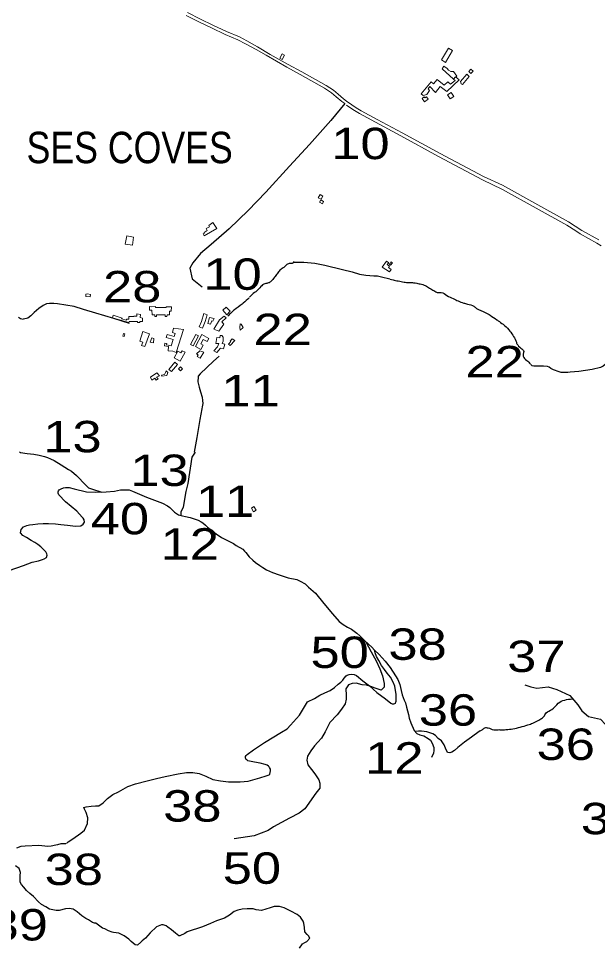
# Model space of a CAD drawing. Extents: x 476989 to 498418, y 4381813 to 4416555.
# Drawn here: x 484677 to 485599, y 4385658 to 4387137 of the extents above; entities that cross this region are included whole.
import ezdxf
from ezdxf.enums import TextEntityAlignment as Align

# ---------------------------------------------------------------- set-up
doc = ezdxf.new("R2010")
doc.units = 0
doc.header["$LTSCALE"] = 20
doc.linetypes.add('MEDIUM_DASHED', pattern=[4.5, 3, -1.5])
for name, color, linetype, lineweight in [('13', 7, 'Continuous', 13), ('36', 7, 'Continuous', 13), ('47', 7, 'Continuous', 13), ('48', 7, 'MEDIUM_DASHED', 13), ('6', 7, 'Continuous', 25)]:
    doc.layers.add(name, color=color, linetype=linetype, lineweight=lineweight)
doc.layers.add('7', color=7, linetype='Continuous')

msp = doc.modelspace()

# ---------------------------------------------------------------- linework, layer by layer
at = {"layer": '36'}
for points in [[(484944.1, 4387141.99), (484964.47, 4387131.61), (484984.32, 4387121.95), (485006.12, 4387111.66), (485026.67, 4387103.08), (485038.55, 4387096.84), (485055.45, 4387087.66), (485071.49, 4387078.37), (485104.22, 4387059.29), (485125.9, 4387047.57), (485164.72, 4387025.8), (485175.49, 4387018.62), (485182.86, 4387012.44), (485191.84, 4387004.83), (485196.68, 4387001.41)], [(484946.46, 4387146.48), (484966.73, 4387136.15), (484986.51, 4387126.53), (485008.19, 4387116.3), (485028.83, 4387107.68), (485040.94, 4387101.32), (485057.93, 4387092.09), (485077.85, 4387079.8), (485106.7, 4387063.72), (485128.35, 4387052.02), (485167.37, 4387030.13), (485178.54, 4387022.69), (485186.13, 4387016.32), (485194.95, 4387008.84), (485199.56, 4387005.59), (485207.95, 4386999.32), (485214.97, 4386994.81), (485222.72, 4386990.21), (485248.09, 4386976.31), (485288.29, 4386954.73), (485348.62, 4386921.76), (485417.64, 4386885.14), (485448.2, 4386871.57)], [(485199.66, 4386999.18), (485205.06, 4386995.15), (485212.3, 4386990.49), (485220.21, 4386985.8), (485245.67, 4386971.85), (485285.88, 4386950.27), (485346.2, 4386917.3), (485416.17, 4386880.07), (485448.2, 4386864.89)], [(485448.2, 4386871.57), (485504.34, 4386840.28), (485553.22, 4386813.06), (485574.47, 4386799.34), (485601.49, 4386784.39)], [(485448.2, 4386864.89), (485501.51, 4386835.18), (485550.21, 4386808.06), (485564.49, 4386798.84)], [(485564.49, 4386798.84), (485571.47, 4386794.33), (485598.37, 4386779.45), (485604.95, 4386774.75)]]:
    msp.add_lwpolyline(points, dxfattribs=at)
at = {"layer": '47'}
for points in [[(485097.24, 4387080.64), (485100.57, 4387078.42), (485096.97, 4387071.84), (485093.08, 4387073.8)], [(485368.22, 4387086.2), (485357.27, 4387067.19), (485350.67, 4387071.13), (485362.11, 4387089.78)], [(485391.11, 4387048.23), (485395.02, 4387044.71), (485384.02, 4387031.63), (485382.12, 4387032.82), (485380.94, 4387036.71)], [(485394.39, 4387052.63), (485397.68, 4387049.39), (485401.01, 4387052.87), (485397.7, 4387056.05)], [(485372.99, 4387044.3), (485379, 4387039.44), (485359.12, 4387020.48), (485348.48, 4387028.62), (485341.4, 4387019.09), (485332.09, 4387028.81), (485329.57, 4387025.05), (485331.9, 4387022.2), (485327.68, 4387016.19), (485321.58, 4387014.58), (485318.65, 4387016.84), (485334.49, 4387035.93), (485338.08, 4387032.94), (485343.81, 4387040.06), (485355.18, 4387030.96), (485360.7, 4387036.3), (485365.34, 4387032.5), (485372.61, 4387038.49), (485370.16, 4387040.56)], [(485366.04, 4387018.89), (485370.57, 4387012.53), (485364.64, 4387009.06), (485360.3, 4387015.36)], [(485327, 4387012.45), (485329.8, 4387008.42), (485323.53, 4387004.21), (485319.77, 4387009.59), (485323.16, 4387012.07), (485324.25, 4387010.89)], [(485159.11, 4386849.19), (485161.77, 4386854.02), (485157.33, 4386856.45), (485154.56, 4386851.45)], [(485158.77, 4386848.3), (485163.02, 4386845.74), (485161.19, 4386841.81), (485156.57, 4386844.26)], [(484986.77, 4386812.07), (484993.03, 4386802.65), (484972.62, 4386790.82), (484971.23, 4386794), (484973.4, 4386795.11), (484972.72, 4386796.45), (484977.43, 4386799.32), (484975.89, 4386802.33), (484981.16, 4386805.24), (484980.03, 4386807.2)], [(484849.44, 4386790.77), (484846.94, 4386777.85), (484858.51, 4386775.82), (484860.5, 4386788.91)], [(485267.8, 4386733.43), (485256.48, 4386741.12), (485263.36, 4386750.59), (485266.67, 4386747.96), (485264.52, 4386745.08), (485268.18, 4386742.35), (485266.49, 4386740.36), (485270.62, 4386737.25)], [(485272.72, 4386747.91), (485269.84, 4386744.21), (485268.02, 4386745.4), (485269.25, 4386747.04), (485268.91, 4386747.33), (485270.37, 4386749.54)], [(484791.59, 4386697.69), (484791.41, 4386693.78), (484784.36, 4386694.03), (484784.57, 4386697.72), (484787.22, 4386698.3)], [(484874.65, 4386654.69), (484870.48, 4386654.58), (484870.46, 4386653.02), (484866.58, 4386653.01), (484866.49, 4386654.59), (484853.21, 4386654.39), (484852.68, 4386652.83), (484826.61, 4386660.29), (484827.71, 4386664.28), (484842.06, 4386659.71), (484841.42, 4386658.6), (484849.07, 4386656.47), (484849.11, 4386658.07), (484852.95, 4386658.16), (484852.97, 4386662.54), (484860.65, 4386662.23), (484860.59, 4386662.87), (484865.39, 4386662.92), (484865.39, 4386666.55), (484871.56, 4386665.85), (484871.09, 4386660.58), (484874.62, 4386659.92)], [(484912.38, 4386677.94), (484920.75, 4386677.78), (484920.46, 4386671.05), (484917.81, 4386671.05), (484917.39, 4386664.88), (484913.7, 4386664.88), (484913.51, 4386662.27), (484910.67, 4386662.23), (484910.82, 4386664.83), (484896.88, 4386664.88), (484896.69, 4386662.27), (484894.26, 4386662.29), (484894.38, 4386664.94), (484889.81, 4386664.95), (484889.46, 4386672.4), (484885.79, 4386672.68), (484885.72, 4386678.1), (484888.41, 4386678.06), (484895.26, 4386678.11), (484895.2, 4386676.96), (484912.45, 4386676.68)], [(484965.07, 4386645.88), (484968.64, 4386654.55), (484972.34, 4386666.93), (484977.49, 4386665.02), (484974.53, 4386654.43), (484969.91, 4386643.72)], [(485009.06, 4386664.93), (485002.56, 4386672.56), (485007.64, 4386677.52), (485014.09, 4386671.17)], [(484982.82, 4386649.95), (484978.55, 4386651.27), (484981.38, 4386660.9), (484988.94, 4386659.2), (484986.79, 4386654.97), (484985.12, 4386655.57)], [(484996.43, 4386639.1), (484988.3, 4386642.47), (484997.48, 4386657.34), (485004.88, 4386662.98), (485007.91, 4386660.32), (485001.03, 4386653.8), (485004.26, 4386650.11)], [(485030.11, 4386650.61), (485029.58, 4386644.86), (485029.99, 4386640.89), (485034.75, 4386645), (485031.79, 4386649.97)], [(484844.5, 4386635.18), (484846.55, 4386634.63), (484845.65, 4386630.54), (484843.47, 4386631)], [(484878.58, 4386614.5), (484885.94, 4386635.06), (484875.22, 4386638.61), (484870.18, 4386623.37), (484875.16, 4386621.77), (484873.26, 4386616.47)], [(484928.18, 4386605.08), (484939.97, 4386641.51), (484923.72, 4386643.6), (484923.72, 4386643.6), (484922.15, 4386636.75), (484926.42, 4386635.39), (484924.89, 4386630.56), (484914.1, 4386633.92), (484912.38, 4386628.99), (484923.2, 4386626.01), (484920.36, 4386615.87), (484913.03, 4386617.33), (484913.16, 4386619.43), (484910.06, 4386619.81), (484909.64, 4386615.9), (484916.17, 4386614.67), (484915.69, 4386607.82), (484923.12, 4386607.18)], [(484963.89, 4386631.61), (484955.07, 4386615.72), (484950.82, 4386617.68), (484959.38, 4386633.93)], [(484886.83, 4386621.49), (484889.37, 4386628.45), (484892.44, 4386627.58), (484892, 4386620.32)], [(484967.69, 4386609.95), (484958.91, 4386614.38), (484968.97, 4386633.65), (484980.35, 4386627.47), (484977.58, 4386622.58), (484971.41, 4386625.97), (484967.47, 4386618.74), (484971.14, 4386616.66)], [(484988.42, 4386607.8), (484994.31, 4386613.95), (484996.03, 4386619.44), (484991.42, 4386619.37), (484993.16, 4386629.13), (484997.81, 4386628.54), (484998.06, 4386632.15), (485000.73, 4386632.13), (485003.26, 4386629.33), (485003.18, 4386623.16), (485001.26, 4386619.51), (485005.92, 4386618.3), (485003.83, 4386610.74), (484998.71, 4386611.89), (484992.95, 4386605.26)], [(485011.45, 4386618.18), (485014.46, 4386616.41), (485021.54, 4386624.32), (485017.31, 4386627), (485014.34, 4386623.18), (485015.15, 4386622.6)], [(484930.93, 4386607.22), (484924.86, 4386596.58), (484934.84, 4386591.38), (484942.38, 4386605.69), (484937.68, 4386607.95), (484935.78, 4386604.53)], [(484966.64, 4386595.92), (484972.22, 4386605.45), (484965.86, 4386607.86), (484960.42, 4386603.19), (484963.09, 4386601.11), (484961.54, 4386598.91)], [(484930.53, 4386586.08), (484920.88, 4386574.84), (484916.58, 4386578.14), (484926.15, 4386589.6)], [(484911.46, 4386573.35), (484909.91, 4386569.85), (484905.06, 4386569.06), (484905.54, 4386567.13), (484913.36, 4386568.57), (484915.04, 4386573.28), (484912.15, 4386575.78)], [(484931.93, 4386579.1), (484935.2, 4386575.97), (484938.33, 4386579.24), (484934.89, 4386582.26)], [(484897.59, 4386572.87), (484901.46, 4386567.77), (484897.1, 4386566.06), (484899.31, 4386562.89), (484896.16, 4386560.94), (484894.13, 4386564.12), (484889.43, 4386560.81), (484887.27, 4386565.75)]]:
    msp.add_lwpolyline(points, close=True, dxfattribs=at)
msp.add_lwpolyline([(485370.16, 4387040.56), (485352.1, 4387056.87), (485354.61, 4387061.18), (485359.78, 4387057.35), (485362.15, 4387054.85), (485365.59, 4387052.79), (485369.74, 4387052.73), (485375.25, 4387045.3), (485374.01, 4387043.48)], dxfattribs=at)
at = {"layer": '48'}
msp.add_lwpolyline([(485047.97, 4386357.07), (485051.39, 4386351.42), (485055.76, 4386354.03), (485052.03, 4386360.03)], close=True, dxfattribs=at)
at = {"layer": '6'}
for points in [[(485196.68, 4387001.41), (485174.53, 4386974.43), (485140.42, 4386936.16), (485108.67, 4386902.09), (485070.95, 4386860.47), (485042.96, 4386831.45), (485012.41, 4386802.17), (484984.19, 4386777.31), (484966.85, 4386762.96), (484954.68, 4386748.08), (484950.17, 4386739.57), (484953.68, 4386722.28), (484969.49, 4386709.51)], [(485115.8, 4386749.57), (485116.23, 4386749.1), (485119.88, 4386748.84), (485125.2, 4386748.79), (485131.48, 4386748.94), (485148.96, 4386747.36), (485165.08, 4386743.99), (485193.34, 4386737.28), (485208.6, 4386733.52), (485219.97, 4386729.79), (485230.45, 4386728.1), (485243, 4386727.43), (485248.7, 4386726.99), (485255.02, 4386725.5), (485268.69, 4386722.23)], [(484853.83, 4386651.43), (484829.07, 4386659.2), (484800.41, 4386667.98), (484780.66, 4386673.63), (484765.62, 4386678.12), (484752.26, 4386680.6), (484739.16, 4386682.53), (484733.6, 4386683.05), (484726.44, 4386683.19), (484721.56, 4386682.61), (484716.47, 4386680.06), (484709.49, 4386675.03), (484701.94, 4386668.98), (484696.71, 4386663.28), (484692.09, 4386660), (484689.62, 4386659.03), (484684.79, 4386658.31)], [(484677.03, 4386661.52), (484680.13, 4386659.31), (484684.79, 4386658.31)], [(484996.82, 4386599.17), (484987.66, 4386591.04), (484966.55, 4386571), (484963.37, 4386567.3), (484963.02, 4386566.37), (484962.82, 4386558.23), (484964.9, 4386549.85), (484966.92, 4386542.55), (484969.46, 4386533.86), (484970.42, 4386528.49), (484970.53, 4386524.01), (484969.46, 4386518.29), (484968.88, 4386515.18), (484965.99, 4386498.52), (484961.18, 4386469.77), (484956.92, 4386446.46)], [(485614.42, 4386588.88), (485608.24, 4386583.25), (485603.79, 4386581.02), (485590.67, 4386577.99), (485569.57, 4386574.82), (485555.53, 4386573.67), (485552.14, 4386573.42), (485549.36, 4386573.22), (485546.88, 4386573.26), (485541.5, 4386573.42), (485538.28, 4386574.27), (485529.3, 4386577.31), (485524.93, 4386579.57), (485522.13, 4386581.47), (485519.82, 4386582.6), (485513.12, 4386583.13), (485507.1, 4386583.36), (485502.68, 4386583.42), (485498.06, 4386583.56), (485495.44, 4386583.92), (485492.88, 4386586.05)], [(484678.9, 4386446.99), (484680.33, 4386445.85), (484691.09, 4386444.37), (484701.51, 4386443.23), (484710.08, 4386441.49), (484718.53, 4386439.37), (484723.57, 4386437.83), (484728.11, 4386435.66), (484734.03, 4386433), (484745.31, 4386426.03), (484756.55, 4386418.6), (484761.33, 4386415.93), (484769.5, 4386409.28), (484784.5, 4386393.85), (484788.56, 4386389.73), (484793.23, 4386388.09), (484809.87, 4386382.9)], [(484958.3, 4386446.26), (484953.04, 4386438.59), (484946.62, 4386396.38), (484943.54, 4386383.67), (484939.22, 4386358.89), (484937.9, 4386355.26), (484935.85, 4386351.35), (484935.78, 4386345.49)], [(484685.19, 4386265.93), (484699.05, 4386271.21), (484709.17, 4386273.3), (484715.34, 4386275.16), (484718.26, 4386276.38), (484721.48, 4386278.67), (484722.61, 4386282.28), (484722.26, 4386284.54), (484720.47, 4386287.55), (484712.75, 4386295.74), (484708.14, 4386299.06), (484702.94, 4386302.54), (484697.3, 4386305.69), (484689.87, 4386310.65), (484683.82, 4386313.61), (484680.3, 4386317.64), (484681.25, 4386322.94), (484685, 4386327.62), (484690.15, 4386329.65), (484694.88, 4386330.51), (484699.71, 4386331.42), (484707.82, 4386332.39), (484716.34, 4386332.7), (484724.64, 4386332.71), (484735.89, 4386332.21), (484744.5, 4386331.21), (484755.17, 4386329.99), (484767.77, 4386328.32), (484776.22, 4386328.88), (484780.04, 4386331.64), (484782.17, 4386335), (484781.89, 4386338.8), (484780.11, 4386341.21), (484778.3, 4386343.08), (484770.28, 4386352.19), (484752.12, 4386367.49), (484741.53, 4386378.26), (484740.11, 4386380.91), (484740.18, 4386383.41), (484740.83, 4386384.77), (484742.14, 4386386.31), (484744.9, 4386388.13), (484748.72, 4386389.71), (484752.02, 4386390.1), (484757.64, 4386389.92), (484765.75, 4386388.13), (484785.25, 4386383.31), (484799.6, 4386382.75), (484816.87, 4386383.07), (484829.76, 4386384.43), (484839.45, 4386386.17), (484849.35, 4386386.59), (484853.26, 4386386.23), (484858.54, 4386384.32), (484881.13, 4386374.95), (484906.55, 4386365.25), (484914.67, 4386360.86), (484918.39, 4386358.2), (484925.44, 4386350.65), (484931.98, 4386346.41), (484938.51, 4386345.07), (484942.87, 4386343.84)], [(484942.87, 4386343.84), (484950.32, 4386342.24), (484955.52, 4386340.89), (484963.01, 4386337.82), (484967.78, 4386335.39), (484970.48, 4386333.62), (484974.91, 4386330.09), (484978.3, 4386327.13), (484983.78, 4386322.85), (484991.83, 4386316.23), (485000.22, 4386310.65), (485010.22, 4386305.49), (485019.61, 4386300.9), (485023.89, 4386297.97), (485034.3, 4386291.84), (485037.17, 4386288.93), (485039.13, 4386286.4), (485044.46, 4386279.63), (485050.26, 4386274.45), (485054.6, 4386270.52), (485061.48, 4386265.69), (485066.31, 4386262.9), (485072.11, 4386258.98), (485081.56, 4386254.75), (485092.29, 4386251), (485106.38, 4386246.15), (485120.38, 4386243.3), (485125.75, 4386241.04), (485133.62, 4386236.48), (485138.8, 4386231.28), (485150.15, 4386221.79), (485163.42, 4386205.22), (485177.27, 4386188.83), (485187.8, 4386176.49), (485194.39, 4386172.03), (485200.95, 4386167.78), (485207.56, 4386164.49), (485215.71, 4386158.18), (485220.87, 4386153.67), (485228.5, 4386145.73), (485239.66, 4386135.6), (485243.92, 4386131.21)], [(484662.04, 4386258.08), (484685.19, 4386265.93)], [(485230.17, 4386144.48), (485238.93, 4386128.18), (485246.9, 4386114.26), (485252.47, 4386101.54), (485256.85, 4386090.01), (485259.24, 4386078.08), (485259.64, 4386072.11), (485254.86, 4386067.34), (485244.91, 4386070.52), (485238.14, 4386073.31), (485231.37, 4386075.3), (485224.2, 4386075.69), (485214.64, 4386078.48), (485208.67, 4386078.08), (485202.69, 4386075.69), (485198.31, 4386069.33), (485199.11, 4386059.57), (485198.71, 4386052.8), (485197.12, 4386045.64), (485191.54, 4386036.89), (485184.77, 4386028.13), (485173.22, 4386015.8), (485165.66, 4386001.18), (485159.68, 4385990.84), (485153.71, 4385984.47), (485148.53, 4385978.9), (485142.56, 4385970.54), (485137.38, 4385962.19), (485136.19, 4385955.82), (485138.18, 4385948.66), (485143.75, 4385941.1), (485149.33, 4385933.93), (485155.7, 4385924.38), (485156.89, 4385919), (485156.89, 4385911.43), (485150.92, 4385903.48), (485133, 4385878.41), (485124.24, 4385871.64), (485108.82, 4385863.4), (485083.33, 4385849.87), (485074.57, 4385843.9), (485052.27, 4385835.14), (485020.41, 4385830.77)], [(485137.42, 4386048.97), (485148.63, 4386053.82), (485157.15, 4386059.18), (485164.93, 4386062.86), (485173.69, 4386066.86), (485180.28, 4386071.55), (485186.41, 4386076.63), (485190.45, 4386080.03), (485193.63, 4386083.43), (485195.76, 4386086.35), (485199.08, 4386090.25), (485200.34, 4386091.24), (485203.86, 4386092.43), (485208.21, 4386092.7), (485211.9, 4386092.03), (485215.19, 4386090.42), (485225.5, 4386082.35), (485236.31, 4386074.25), (485247.96, 4386063.67), (485261.46, 4386053.34), (485269.97, 4386046.64), (485272.18, 4386045.77), (485274.75, 4386045.53), (485276.27, 4386045.91), (485277.39, 4386046.58), (485277.29, 4386046.46), (485277.27, 4386046.28), (485277.91, 4386048.23), (485278.42, 4386049.78), (485278.61, 4386055.69), (485278.62, 4386060.86), (485277.55, 4386067.01), (485276.23, 4386073.52), (485274, 4386079.95), (485269.68, 4386088.07), (485264.45, 4386094.26), (485259.77, 4386100.29), (485255.39, 4386106.74), (485251.08, 4386114.81), (485247.23, 4386121.17), (485244.96, 4386126.54), (485243.92, 4386131.21)], [(485244.01, 4386130.88), (485251.73, 4386124.05), (485261.17, 4386113.52), (485269.16, 4386103.38), (485277.47, 4386090.36), (485281.02, 4386084.45), (485284.58, 4386076.08), (485286.34, 4386066.85), (485288.02, 4386059.68), (485291.51, 4386051.58), (485293.26, 4386046.93), (485295.26, 4386040.29), (485298.32, 4386028.5), (485299.16, 4386022.88), (485301.83, 4386015.45), (485307.25, 4386003.05), (485311.27, 4385998.43), (485316.17, 4385996.13), (485322.45, 4385994.43), (485329.69, 4385990.5), (485333.27, 4385987.49), (485336.16, 4385982.91), (485338.39, 4385976.12), (485338.64, 4385971.4), (485337.85, 4385966.8), (485334.87, 4385960.03)], [(485483.32, 4386075.85), (485492.95, 4386072.64), (485502.59, 4386070.51), (485520.79, 4386072.64), (485534.7, 4386068.37), (485555.04, 4386058.75), (485567.89, 4386043.78), (485574.31, 4386034.16), (485585.02, 4386025.61), (485604.29, 4386021.34), (485611.78, 4386012.79), (485612.86, 4385999.96), (485619.28, 4385980.72)], [(484753.57, 4385823.35), (484756.07, 4385825.8), (484763.83, 4385830.53), (484776.58, 4385839.37), (484782.34, 4385844.43), (484787.2, 4385854.84), (484787.51, 4385863.86), (484784.87, 4385872.53), (484782.19, 4385877.63), (484780.99, 4385880.64), (484784.76, 4385881.31), (484793.02, 4385882.42), (484799.69, 4385882.89), (484804.87, 4385883.25), (484812.21, 4385887.91), (484818.61, 4385894.93), (484827.29, 4385900.91), (484836.49, 4385905.57), (484851.49, 4385914.04), (484863.4, 4385918.36), (484882.15, 4385922.96), (484896.7, 4385926.47), (484910.78, 4385929.65), (484931.26, 4385933.88), (484944.85, 4385936.14), (484954.98, 4385936.35), (484964.69, 4385934.66), (484975.5, 4385930.27), (484986.54, 4385925.21), (484998.58, 4385922.91), (485011.63, 4385921.23), (485030.11, 4385921.12), (485042.66, 4385922.44), (485061.41, 4385927.72), (485071.46, 4385930.94), (485074.81, 4385932.11), (485076.32, 4385932.73), (485076.79, 4385932.96), (485077.28, 4385933.45), (485078.11, 4385936.24), (485078.35, 4385938.73), (485078.24, 4385941.42), (485077.1, 4385943.96), (485076.09, 4385945.28), (485075.2, 4385946.11), (485073.05, 4385947.62), (485070.18, 4385948.95), (485061.85, 4385950.92), (485052.97, 4385952.73), (485042.57, 4385954.94), (485040.72, 4385956.12), (485039.31, 4385957.48), (485038.69, 4385959.31), (485038.59, 4385960.67), (485038.85, 4385961.89), (485039.56, 4385963.1), (485041.35, 4385965.05), (485051.42, 4385972.39), (485069, 4385983.72), (485096.24, 4386000.56), (485104.76, 4386005.49), (485110.15, 4386011.63), (485124.59, 4386027.56), (485137.59, 4386048.93)], [(485360.44, 4385967.89), (485357.02, 4385975.21), (485355.18, 4385980.08), (485350.75, 4385986.5), (485345.66, 4385990.53), (485341.11, 4385995.13), (485337.24, 4385997.82), (485332.38, 4385999.2), (485327.57, 4386000.86), (485318.71, 4386002.15), (485313.97, 4386002.06), (485308.63, 4386001.53)], [(485410.77, 4386001.69), (485398.53, 4385992.68), (485387.19, 4385984.33), (485376.75, 4385975.81), (485371.33, 4385971.08), (485367.37, 4385968.65), (485364.11, 4385967.7), (485360.44, 4385967.89)], [(484674.66, 4385816.15), (484681.59, 4385818.87), (484687.68, 4385819.41), (484687.98, 4385819.58), (484709.29, 4385820.21), (484723.73, 4385818.84), (484729.17, 4385819.65), (484736.43, 4385820.77), (484740.02, 4385821.59), (484744.86, 4385823.22), (484752.62, 4385823.08)], [(484800.3, 4385696.28), (484798.02, 4385696.13), (484794.95, 4385697.11), (484788.65, 4385701.33), (484784.14, 4385703.65), (484778.1, 4385707.87), (484770.66, 4385714.12), (484763.99, 4385718.53), (484757.75, 4385719.78), (484751.75, 4385719.07), (484741.98, 4385716.54), (484737.22, 4385716.32), (484726.74, 4385718.66), (484720.63, 4385722.11), (484713.97, 4385725.94), (484709.05, 4385730.17), (484700.76, 4385738.7), (484695.42, 4385743.75), (484690.09, 4385748.53), (484685.65, 4385753.67), (484681.68, 4385758.04), (484679.8, 4385761.6), (484679.52, 4385766.78), (484679.87, 4385772.29), (484680.17, 4385776.84), (484679.5, 4385780.26), (484677.94, 4385783.18), (484672.46, 4385787.45)], [(485124.79, 4385656.54), (485129.25, 4385663.08), (485133.36, 4385665.71), (485136.36, 4385667.21), (485141.15, 4385672.45), (485138.98, 4385676.34), (485136.6, 4385678.19), (485132.96, 4385682.34), (485132.73, 4385689.27), (485131.61, 4385696.11), (485130.61, 4385699.3), (485126.06, 4385705.79), (485120.96, 4385709.83), (485110.68, 4385715.36), (485102.13, 4385719.83), (485100.43, 4385720.52), (485092.99, 4385723.04), (485084.43, 4385722.63), (485077.87, 4385720.89), (485071.23, 4385718.34), (485064, 4385716.41), (485055.4, 4385717.72), (485051.11, 4385718.81), (485041.54, 4385719.28), (485033.36, 4385718.73), (485026.4, 4385717.08), (485020.65, 4385715.06), (485013.23, 4385708.97), (485004.94, 4385704.27), (484992.48, 4385699.86), (484982.68, 4385695.78), (484970.33, 4385690.54), (484945.93, 4385682.49), (484941.89, 4385679.67), (484934.03, 4385676.17), (484932.74, 4385676.12), (484927.13, 4385680.21), (484921, 4385685.64), (484914.97, 4385689.73), (484912.08, 4385691.8), (484907.48, 4385693.68), (484904.82, 4385693.81), (484897.05, 4385690.33), (484887.01, 4385681), (484879.15, 4385672.55), (484873.88, 4385668.07), (484872, 4385666.15), (484866.47, 4385661.44), (484862.95, 4385661.58), (484856.78, 4385667.28), (484853.08, 4385670.62), (484845.41, 4385676.06), (484837.17, 4385680.06), (484828.17, 4385681.33), (484826.1, 4385681.74), (484820.37, 4385683.92), (484814.41, 4385687.36), (484810.87, 4385688.46), (484804.79, 4385692.89), (484800.15, 4385696.36)]]:
    msp.add_lwpolyline(points, dxfattribs=at)
for points in [[(485115.36, 4386750.06), (485114.19, 4386747.52), (485113.18, 4386746.88), (485109.53, 4386746.71), (485104.69, 4386745.06), (485100.59, 4386741.44), (485096.18, 4386738.34), (485093.43, 4386736.08), (485088.97, 4386730.52), (485084.71, 4386724.86), (485079.08, 4386718.3), (485075.29, 4386715.77), (485069.5, 4386714.61), (485062.95, 4386709.95), (485056.92, 4386703.52), (485049.07, 4386697.32), (485044.98, 4386693.19)], [(485269.25, 4386721.86), (485273.58, 4386720.69), (485281.99, 4386718.99), (485291.13, 4386717.08), (485298.97, 4386716.54), (485306.16, 4386716.18), (485311.27, 4386715.46), (485318.78, 4386713.76), (485326.94, 4386710.61), (485333.63, 4386706.4), (485340.32, 4386702.69), (485343.71, 4386700.79), (485350.33, 4386700.57), (485359.32, 4386695.9), (485369.58, 4386690.94), (485377.37, 4386687.13), (485386.17, 4386683.79), (485392.17, 4386682.32), (485402.4, 4386678.62), (485406.74, 4386675.4), (485420.48, 4386668.69), (485428.53, 4386664.29), (485438.68, 4386657.3), (485441.05, 4386655.72), (485448.83, 4386650.03), (485458.08, 4386641.35), (485464.26, 4386632.88), (485469.2, 4386623.92), (485470.98, 4386618.97), (485477.37, 4386612.21), (485481.67, 4386606.48), (485480.65, 4386601.56), (485480.95, 4386599.19), (485486.47, 4386592.56), (485492.66, 4386586.48)], [(485044.48, 4386692.16), (485035.19, 4386683.87), (485033.34, 4386682.1), (485020.94, 4386672.97), (485016.38, 4386668.89), (485010.36, 4386663.05)], [(485443.74, 4386004.16), (485443.83, 4386004.15), (485453.51, 4386004.46), (485464.41, 4386005.81), (485476.23, 4386008.42), (485488.14, 4386011.85), (485496.43, 4386014.96), (485508.98, 4386021.45), (485513.76, 4386025.14), (485517.53, 4386031.09), (485526.61, 4386036.58), (485536.73, 4386046.57), (485559.1, 4386053.59)], [(485443.74, 4386004.16), (485434.22, 4386003.76), (485425.36, 4386006.76), (485422.62, 4386007.16), (485419.49, 4386006.67), (485415.18, 4386003.87), (485410.89, 4386001.79)]]:
    msp.add_spline(points, degree=3, dxfattribs=at)

# ---------------------------------------------------------------- texts
at = {"layer": '13', "width": 1.25}
for s, p in [('10', (485221.71, 4386912.99)), ('10', (485018.06, 4386704.9)), ('28', (484858.22, 4386684.95)), ('22', (485097.88, 4386616.91)), ('22', (485435.5, 4386565.58)), ('11', (485046.7, 4386519.24)), ('13', (484763.07, 4386446.16)), ('13', (484901.82, 4386392.49)), ('11', (485006.11, 4386343.25)), ('40', (484838.61, 4386315.54)), ('12', (484949.89, 4386275.21)), ('38', (485312.74, 4386115.62)), ('50', (485188.67, 4386102.67)), ('37', (485501.81, 4386096.28)), ('36', (485361.09, 4386010.77)), ('36', (485548.73, 4385956.2)), ('12', (485275.65, 4385934.42)), ('38', (484954.01, 4385858.01)), ('37', (485619.21, 4385837.89)), ('38', (484765.19, 4385757.02)), ('50', (485048.84, 4385758.93)), ('39', (484677.48, 4385668.68))]:
    msp.add_text(s, height=50, dxfattribs=at).set_placement(p, align=Align.CENTER)
at = {"layer": '7', "width": 0.85}
msp.add_text('SES COVES', height=50, dxfattribs=at).set_placement((484854.14, 4386906.57), align=Align.CENTER)

doc.saveas('drawing.dxf')
